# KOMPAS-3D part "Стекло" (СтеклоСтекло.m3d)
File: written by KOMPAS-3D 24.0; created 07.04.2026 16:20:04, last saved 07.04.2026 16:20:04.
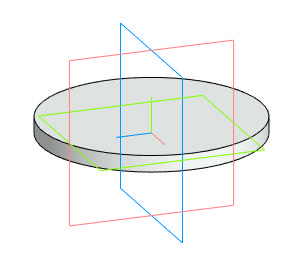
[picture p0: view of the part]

Document properties: Автор: Main; Полное имя файла: D:\DN.ru Аутсерс\Стекло смотровое DN.ru\Исходники\Стекло смотровое DN.ru SG2-34G-F тип В ГОСТ 21836-2021 Ду40 Ру40, углеродистая сталь, фланцевое\СтеклоСтекло.m3d

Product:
- Body: Твердое тело1  | qty 1
- Part/product: Стекло

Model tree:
1. Твердое тело1  (labels: Твердое тело1)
